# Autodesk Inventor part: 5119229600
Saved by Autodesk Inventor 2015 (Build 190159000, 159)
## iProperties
Created: 2020-07
Part Number: 5119229600
Checked By: TraceParts S.A.
Material: Generic
Catalog Web Link: www.traceparts.com
Document SubType Name: Modeling
Designer: TraceParts
Density: 1 g/cm^3
Appearance: Default
Company: TraceParts S.A.
Author: TraceParts
REFERENCE: 5119229600
SUPPLIER: Soler & Palau
DESIGN: HIB-800 P 0,55KW (230V 50HZ) - 5119229600
TraceParts.PartNumber: 10-20122018-119595
TRACEPARTS: TRACEPARTS
TraceParts.PartTitle: HIB-P/HIT-P
TraceParts.InstanceId: 10-20122018-1195953JOXUOUVT8TXEMYWTT7NHPV9
TraceParts.PartLanguage: en
TraceParts.ClassPath: SOLER_PALAU:10-20122018-119595
TraceParts.PartVersion: 1.0.2
TraceParts.PartStatus: Published
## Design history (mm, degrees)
feature "5119229600"
body "Solid1"
